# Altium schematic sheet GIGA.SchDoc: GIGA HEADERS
size A4; CompanyName: Arduino srl; DrawnBy: Silvio Navaretti; DocumentNumber: ASX00039; SheetNumber: 2; SheetTotal: 8; RevAuthor: Silvio Navaretti
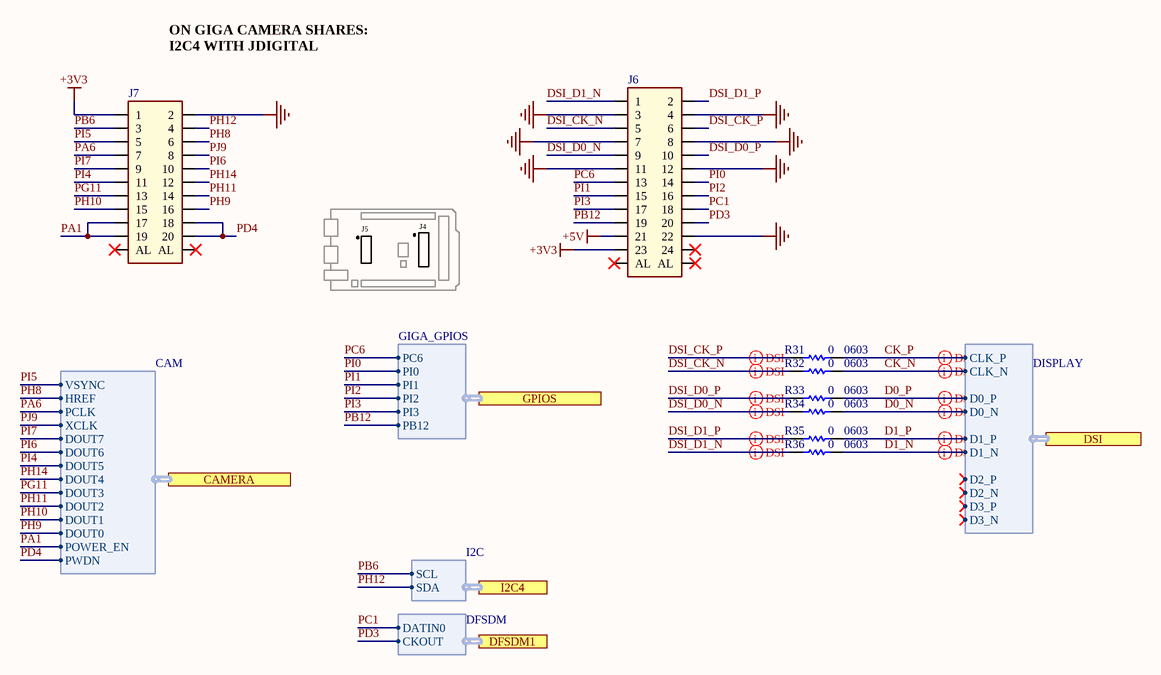
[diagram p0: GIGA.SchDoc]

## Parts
J6  TSM-112-01-F-DV-A-P-FR  [TSM-112-01-F-DV-A-P-FR]  (value not drawn)
J7  TSM-110-01-F-DV-A-P-FR  [TSM-110-01-F-DV-A-P-FR]  (value not drawn)
R31  value 0  Case Code (Imperial): 0603  [RES-0603]  (hidden comment: CRCW06030000Z0EAC)
R32  value 0  Case Code (Imperial): 0603  [RES-0603]  (hidden comment: CRCW06030000Z0EAC)
R33  value 0  Case Code (Imperial): 0603  [RES-0603]  (hidden comment: CRCW06030000Z0EAC)
R34  value 0  Case Code (Imperial): 0603  [RES-0603]  (hidden comment: CRCW06030000Z0EAC)
R35  value 0  Case Code (Imperial): 0603  [RES-0603]  (hidden comment: CRCW06030000Z0EAC)
R36  value 0  Case Code (Imperial): 0603  [RES-0603]  (hidden comment: CRCW06030000Z0EAC)

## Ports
CAMERA (harness CAM), DFSDM1 (harness DFSDM), DSI (harness DISPLAY), GPIOS (harness GIGA_GPIOS), I2C4 (harness I2C)

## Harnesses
CAM: VSYNC, HREF, PCLK, XCLK, DOUT7, DOUT6, DOUT5, DOUT4, DOUT3, DOUT2, DOUT1, DOUT0, POWER_EN, PWDN
I2C: SDA, SCL
DFSDM: DATIN0, CKOUT
GIGA_GPIOS: PC6, PI0, PI1, PI2, PI3, PB12
DISPLAY: CLK_N, CLK_P, D0_N, D0_P, D1_N, D1_P, D2_N, D2_P, D3_N, D3_P

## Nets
+3V3: J6.23 J7.1
+5V: J6.21
GND: J6.3 J6.4 J6.7 J6.8 J6.11 J6.12 J6.22 J7.2
CK_N: R32.2 ; port DSI.CLK_N
CK_P: R31.2 ; port DSI.CLK_P
D0_N: R34.2 ; port DSI.D0_N
D0_P: R33.2 ; port DSI.D0_P
D1_N: R36.2 ; port DSI.D1_N
D1_P: R35.2 ; port DSI.D1_P
DSI_CK_N: J6.5 R32.1
DSI_CK_P: J6.6 R31.1
DSI_D0_N: J6.9 R34.1
DSI_D0_P: J6.10 R33.1
DSI_D1_N: J6.1 R36.1
DSI_D1_P: J6.2 R35.1
PA1: J7.17 J7.19 ; port CAMERA.POWER_EN
PA6: J7.7 ; port CAMERA.PCLK
PB6: J7.3 ; port I2C4.SCL
PB12: J6.19 ; port GPIOS.PB12
PC1: J6.18 ; port DFSDM1.DATIN0
PC6: J6.13 ; port GPIOS.PC6
PD3: J6.20 ; port DFSDM1.CKOUT
PD4: J7.18 J7.20 ; port CAMERA.PWDN
PG11: J7.13 ; port CAMERA.DOUT3
PH8: J7.6 ; port CAMERA.HREF
PH9: J7.16 ; port CAMERA.DOUT0
PH10: J7.15 ; port CAMERA.DOUT1
PH11: J7.14 ; port CAMERA.DOUT2
PH12: J7.4 ; port I2C4.SDA
PH14: J7.12 ; port CAMERA.DOUT4
PI0: J6.14 ; port GPIOS.PI0
PI1: J6.15 ; port GPIOS.PI1
PI2: J6.16 ; port GPIOS.PI2
PI3: J6.17 ; port GPIOS.PI3
PI4: J7.11 ; port CAMERA.DOUT5
PI5: J7.5 ; port CAMERA.VSYNC
PI6: J7.10 ; port CAMERA.DOUT6
PI7: J7.9 ; port CAMERA.DOUT7
PJ9: J7.8 ; port CAMERA.XCLK

Not connected (* = marked no-connect by the designer): J6 24* ALIGN1(AL)* ALIGN2(AL)*; J7 ALIGN1(AL)* ALIGN2(AL)*

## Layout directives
differential pair; differential pair class DSI: CK_N, CK_P, D0_N, D0_P, D1_N, D1_P, DSI_CK_N, DSI_CK_P, DSI_D0_N, DSI_D0_P, DSI_D1_N, DSI_D1_P

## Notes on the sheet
- (near J7) ON GIGA CAMERA SHARES:
  I2C4 WITH JDIGITAL
- J5
- J4

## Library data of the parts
J6 = J0279-A.2: HEADER SMD 2.54mm VERT. 2x012POS ALIGN PINS REEL PICK AND PLACE; Manufacturer: Samtech; Code Arduino: J0279
J7 = J0278-A.2: HEADER SMD 2.54mm VERT. 2x010POS ALIGN PINS REEL PICK AND PLACE; Manufacturer: Samtech; Code Arduino: J0278
R31-R36 = R0096-A.13: RES CHIP 0603 0R 1/10W; Manufacturer: Vishay; Power: 100mW; Tolerance: J; Code Arduino: 0233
